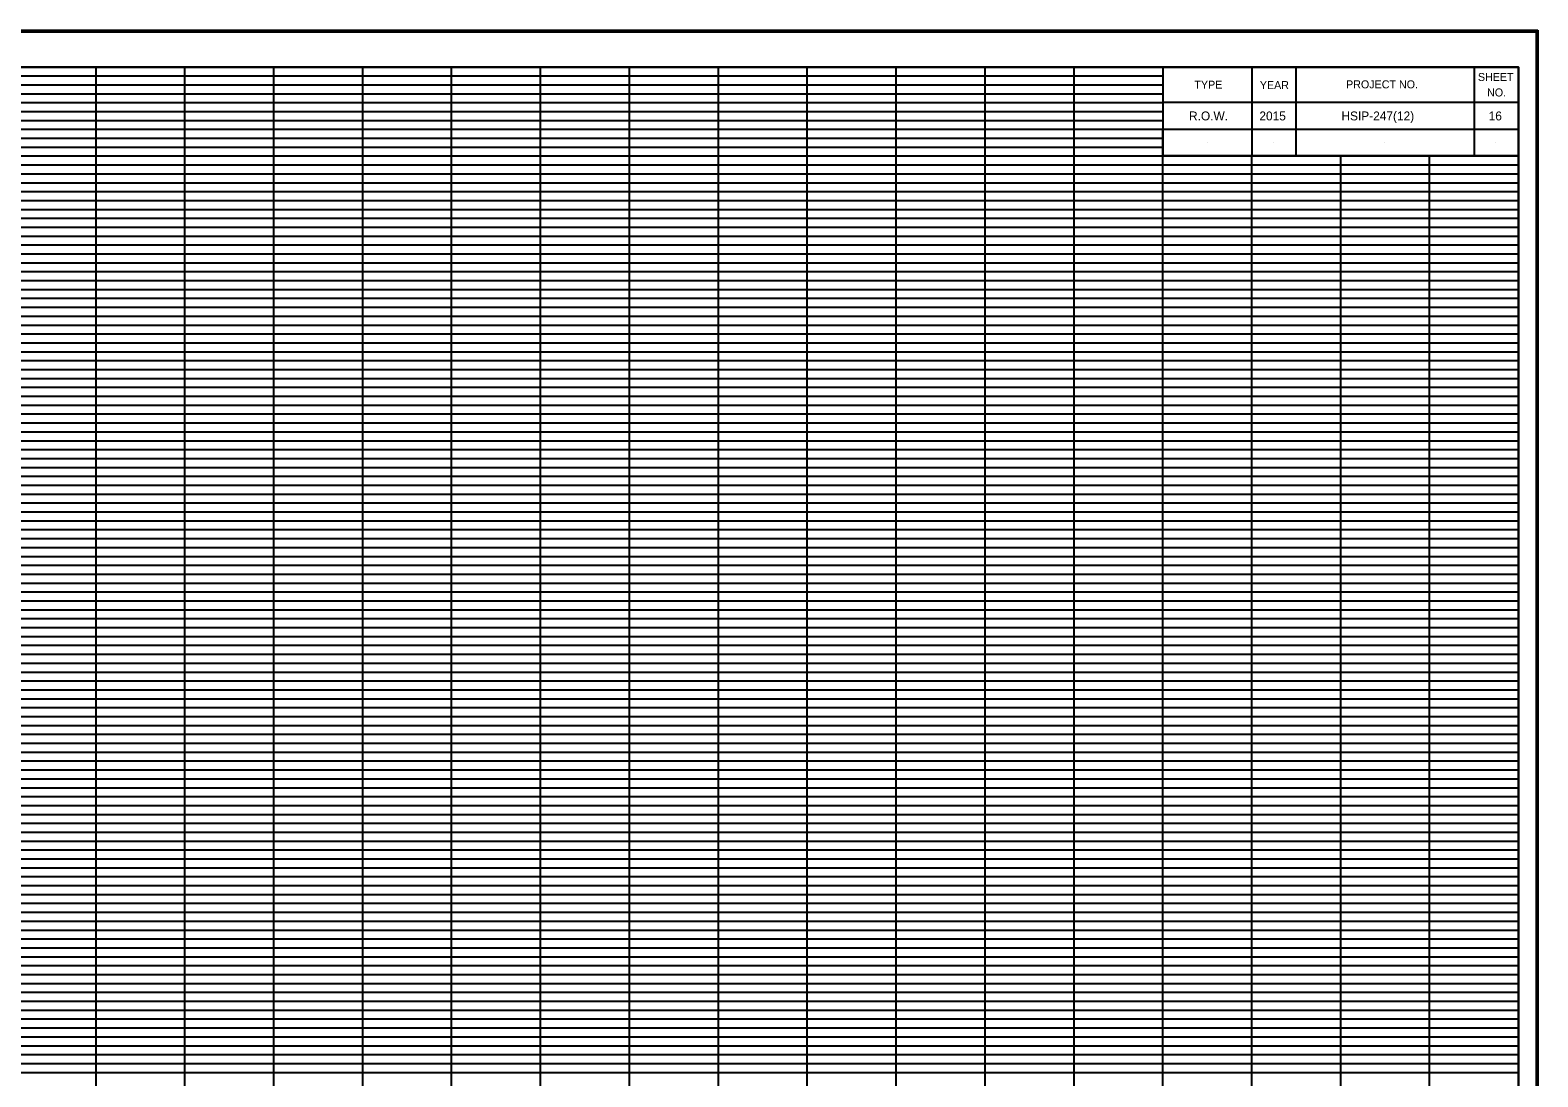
# Model space of a CAD drawing. Extents: x -200 to 1704, y -325 to 2307.
# Drawn here: x 1532.6 to 1702.2, y 1366.5 to 1484.1 of the extents above; entities that cross this region are included whole.
import ezdxf

# ---------------------------------------------------------------- set-up
doc = ezdxf.new("R2010")
doc.units = 0
for name, color, linetype in [('DESIGN - SCRATCH - User 1', 7, 'Continuous'), ('DESIGN - SHEET - Corner Text', 7, 'Continuous'), ('DESIGN - SHEET - Light Grid', 7, 'Continuous'), ('DESIGN - SHEET - Linework', 7, 'Continuous'), ('DESIGN - SHEET - Plot Shape', 7, 'Continuous')]:
    doc.layers.add(name, color=color, linetype=linetype)

msp = doc.modelspace()

# ---------------------------------------------------------------- linework, layer by layer
at = {"layer": 'DESIGN - SCRATCH - User 1'}
for p, q in [((1665, 1474.5), (1665, 1474.5)), ((1672.4, 1474.5), (1672.4, 1474.5)), ((1684.9, 1474.5), (1684.9, 1474.5)), ((1697.4, 1474.5), (1697.4, 1474.5)), ((1665, 1471.5), (1665, 1471.5)), ((1672.4, 1471.5), (1672.4, 1471.5)), ((1684.9, 1471.5), (1684.9, 1471.5)), ((1697.4, 1471.5), (1697.4, 1471.5))]:
    msp.add_line(p, q, dxfattribs=at)
at = {"layer": 'DESIGN - SHEET - Light Grid'}
for p, q in [((1460, 1479), (1540, 1479)), ((1540, 1479), (1620, 1479)), ((1620, 1479), (1660, 1479)), ((1460, 1478), (1540, 1478)), ((1540, 1478), (1620, 1478)), ((1620, 1478), (1660, 1478)), ((1460, 1477), (1540, 1477)), ((1460, 1476), (1540, 1476)), ((1540, 1477), (1620, 1477)), ((1540, 1476), (1620, 1476)), ((1620, 1477), (1660, 1477)), ((1620, 1476), (1660, 1476)), ((1460, 1475), (1540, 1475)), ((1460, 1474), (1540, 1474)), ((1540, 1475), (1620, 1475)), ((1540, 1474), (1620, 1474)), ((1620, 1475), (1660, 1475)), ((1620, 1474), (1660, 1474)), ((1460, 1473), (1540, 1473)), ((1460, 1472), (1540, 1472)), ((1540, 1473), (1620, 1473)), ((1540, 1472), (1620, 1472)), ((1620, 1473), (1660, 1473)), ((1620, 1472), (1660, 1472)), ((1460, 1471), (1540, 1471)), ((1540, 1471), (1620, 1471)), ((1620, 1471), (1660, 1471)), ((1460, 1469), (1540, 1469)), ((1540, 1469), (1620, 1469)), ((1620, 1469), (1700, 1469)), ((1460, 1468), (1540, 1468)), ((1460, 1467), (1540, 1467)), ((1540, 1468), (1620, 1468)), ((1540, 1467), (1620, 1467)), ((1620, 1468), (1700, 1468)), ((1620, 1467), (1700, 1467)), ((1460, 1466), (1540, 1466)), ((1540, 1466), (1620, 1466)), ((1620, 1466), (1700, 1466)), ((1460, 1465), (1540, 1465)), ((1460, 1464), (1540, 1464)), ((1540, 1465), (1620, 1465)), ((1540, 1464), (1620, 1464)), ((1620, 1465), (1700, 1465)), ((1620, 1464), (1700, 1464)), ((1460, 1463), (1540, 1463)), ((1460, 1462), (1540, 1462)), ((1540, 1463), (1620, 1463)), ((1540, 1462), (1620, 1462)), ((1620, 1463), (1700, 1463)), ((1620, 1462), (1700, 1462)), ((1460, 1461), (1540, 1461)), ((1540, 1461), (1620, 1461)), ((1620, 1461), (1700, 1461)), ((1460, 1459), (1540, 1459)), ((1540, 1459), (1620, 1459)), ((1620, 1459), (1700, 1459)), ((1460, 1458), (1540, 1458)), ((1460, 1457), (1540, 1457)), ((1540, 1458), (1620, 1458)), ((1540, 1457), (1620, 1457)), ((1620, 1458), (1700, 1458)), ((1620, 1457), (1700, 1457)), ((1460, 1456), (1540, 1456)), ((1460, 1455), (1540, 1455)), ((1540, 1456), (1620, 1456)), ((1540, 1455), (1620, 1455)), ((1620, 1456), (1700, 1456)), ((1620, 1455), (1700, 1455)), ((1460, 1454), (1540, 1454)), ((1540, 1454), (1620, 1454)), ((1620, 1454), (1700, 1454)), ((1460, 1453), (1540, 1453)), ((1460, 1452), (1540, 1452)), ((1540, 1453), (1620, 1453)), ((1540, 1452), (1620, 1452)), ((1620, 1453), (1700, 1453)), ((1620, 1452), (1700, 1452)), ((1460, 1451), (1540, 1451)), ((1540, 1451), (1620, 1451)), ((1620, 1451), (1700, 1451)), ((1460, 1449), (1540, 1449)), ((1540, 1449), (1620, 1449)), ((1620, 1449), (1700, 1449)), ((1460, 1448), (1540, 1448)), ((1460, 1447), (1540, 1447)), ((1540, 1448), (1620, 1448)), ((1540, 1447), (1620, 1447)), ((1620, 1448), (1700, 1448)), ((1620, 1447), (1700, 1447)), ((1460, 1446), (1540, 1446)), ((1460, 1445), (1540, 1445)), ((1540, 1446), (1620, 1446)), ((1540, 1445), (1620, 1445)), ((1620, 1446), (1700, 1446)), ((1620, 1445), (1700, 1445)), ((1460, 1444), (1540, 1444)), ((1540, 1444), (1620, 1444)), ((1620, 1444), (1700, 1444)), ((1460, 1443), (1540, 1443)), ((1460, 1442), (1540, 1442)), ((1540, 1443), (1620, 1443)), ((1540, 1442), (1620, 1442)), ((1620, 1443), (1700, 1443)), ((1620, 1442), (1700, 1442)), ((1460, 1441), (1540, 1441)), ((1540, 1441), (1620, 1441)), ((1620, 1441), (1700, 1441)), ((1460, 1439), (1540, 1439)), ((1540, 1439), (1620, 1439)), ((1620, 1439), (1700, 1439)), ((1460, 1438), (1540, 1438)), ((1460, 1437), (1540, 1437)), ((1540, 1438), (1620, 1438)), ((1540, 1437), (1620, 1437)), ((1620, 1438), (1700, 1438)), ((1620, 1437), (1700, 1437)), ((1460, 1436), (1540, 1436)), ((1460, 1435), (1540, 1435)), ((1540, 1436), (1620, 1436)), ((1540, 1435), (1620, 1435)), ((1620, 1436), (1700, 1436)), ((1620, 1435), (1700, 1435)), ((1460, 1434), (1540, 1434)), ((1460, 1433), (1540, 1433)), ((1540, 1434), (1620, 1434)), ((1540, 1433), (1620, 1433)), ((1620, 1434), (1700, 1434)), ((1620, 1433), (1700, 1433)), ((1460, 1432), (1540, 1432)), ((1540, 1432), (1620, 1432)), ((1620, 1432), (1700, 1432)), ((1460, 1431), (1540, 1431)), ((1540, 1431), (1620, 1431)), ((1620, 1431), (1700, 1431)), ((1460, 1429), (1540, 1429)), ((1460, 1428), (1540, 1428)), ((1540, 1429), (1620, 1429)), ((1540, 1428), (1620, 1428)), ((1620, 1429), (1700, 1429)), ((1620, 1428), (1700, 1428)), ((1460, 1427), (1540, 1427)), ((1540, 1427), (1620, 1427)), ((1620, 1427), (1700, 1427)), ((1460, 1426), (1540, 1426)), ((1460, 1425), (1540, 1425)), ((1540, 1426), (1620, 1426)), ((1540, 1425), (1620, 1425)), ((1620, 1426), (1700, 1426)), ((1620, 1425), (1700, 1425)), ((1460, 1424), (1540, 1424)), ((1460, 1423), (1540, 1423)), ((1540, 1424), (1620, 1424)), ((1540, 1423), (1620, 1423)), ((1620, 1424), (1700, 1424)), ((1620, 1423), (1700, 1423)), ((1460, 1422), (1540, 1422)), ((1540, 1422), (1620, 1422)), ((1620, 1422), (1700, 1422)), ((1460, 1421), (1540, 1421)), ((1540, 1421), (1620, 1421)), ((1620, 1421), (1700, 1421)), ((1460, 1419), (1540, 1419)), ((1460, 1418), (1540, 1418)), ((1540, 1419), (1620, 1419)), ((1540, 1418), (1620, 1418)), ((1620, 1419), (1700, 1419)), ((1620, 1418), (1700, 1418)), ((1460, 1417), (1540, 1417)), ((1460, 1416), (1540, 1416)), ((1540, 1417), (1620, 1417)), ((1540, 1416), (1620, 1416)), ((1620, 1417), (1700, 1417)), ((1620, 1416), (1700, 1416)), ((1460, 1415), (1540, 1415)), ((1540, 1415), (1620, 1415)), ((1620, 1415), (1700, 1415)), ((1460, 1414), (1540, 1414)), ((1460, 1413), (1540, 1413)), ((1540, 1414), (1620, 1414)), ((1540, 1413), (1620, 1413)), ((1620, 1414), (1700, 1414)), ((1620, 1413), (1700, 1413)), ((1460, 1412), (1540, 1412)), ((1460, 1411), (1540, 1411)), ((1540, 1412), (1620, 1412)), ((1540, 1411), (1620, 1411)), ((1620, 1412), (1700, 1412)), ((1620, 1411), (1700, 1411)), ((1460, 1409), (1540, 1409)), ((1460, 1408), (1540, 1408)), ((1540, 1409), (1620, 1409)), ((1540, 1408), (1620, 1408)), ((1620, 1409), (1700, 1409)), ((1620, 1408), (1700, 1408)), ((1460, 1407), (1540, 1407)), ((1460, 1406), (1540, 1406)), ((1540, 1407), (1620, 1407)), ((1540, 1406), (1620, 1406)), ((1620, 1407), (1700, 1407)), ((1620, 1406), (1700, 1406)), ((1460, 1405), (1540, 1405)), ((1540, 1405), (1620, 1405)), ((1620, 1405), (1700, 1405)), ((1460, 1404), (1540, 1404)), ((1460, 1403), (1540, 1403)), ((1540, 1404), (1620, 1404)), ((1540, 1403), (1620, 1403)), ((1620, 1404), (1700, 1404)), ((1620, 1403), (1700, 1403)), ((1460, 1402), (1540, 1402)), ((1460, 1401), (1540, 1401)), ((1540, 1402), (1620, 1402)), ((1540, 1401), (1620, 1401)), ((1620, 1402), (1700, 1402)), ((1620, 1401), (1700, 1401)), ((1460, 1399), (1540, 1399)), ((1460, 1398), (1540, 1398)), ((1540, 1399), (1620, 1399)), ((1540, 1398), (1620, 1398)), ((1620, 1399), (1700, 1399)), ((1620, 1398), (1700, 1398)), ((1460, 1397), (1540, 1397)), ((1460, 1396), (1540, 1396)), ((1540, 1397), (1620, 1397)), ((1540, 1396), (1620, 1396)), ((1620, 1397), (1700, 1397)), ((1620, 1396), (1700, 1396)), ((1460, 1395), (1540, 1395)), ((1460, 1394), (1540, 1394)), ((1540, 1395), (1620, 1395)), ((1540, 1394), (1620, 1394)), ((1620, 1395), (1700, 1395)), ((1620, 1394), (1700, 1394)), ((1460, 1393), (1540, 1393)), ((1540, 1393), (1620, 1393)), ((1620, 1393), (1700, 1393)), ((1460, 1392), (1540, 1392)), ((1460, 1391), (1540, 1391)), ((1540, 1392), (1620, 1392)), ((1540, 1391), (1620, 1391)), ((1620, 1392), (1700, 1392)), ((1620, 1391), (1700, 1391)), ((1460, 1389), (1540, 1389)), ((1540, 1389), (1620, 1389)), ((1620, 1389), (1700, 1389)), ((1460, 1388), (1540, 1388)), ((1540, 1388), (1620, 1388)), ((1620, 1388), (1700, 1388)), ((1460, 1387), (1540, 1387)), ((1460, 1386), (1540, 1386)), ((1540, 1387), (1620, 1387)), ((1540, 1386), (1620, 1386)), ((1620, 1387), (1700, 1387)), ((1620, 1386), (1700, 1386)), ((1460, 1385), (1540, 1385)), ((1460, 1384), (1540, 1384)), ((1540, 1385), (1620, 1385)), ((1540, 1384), (1620, 1384)), ((1620, 1385), (1700, 1385)), ((1620, 1384), (1700, 1384)), ((1460, 1383), (1540, 1383)), ((1540, 1383), (1620, 1383)), ((1620, 1383), (1700, 1383)), ((1460, 1382), (1540, 1382)), ((1460, 1381), (1540, 1381)), ((1540, 1382), (1620, 1382)), ((1540, 1381), (1620, 1381)), ((1620, 1382), (1700, 1382)), ((1620, 1381), (1700, 1381)), ((1460, 1379), (1540, 1379)), ((1540, 1379), (1620, 1379)), ((1620, 1379), (1700, 1379)), ((1460, 1378), (1540, 1378)), ((1460, 1377), (1540, 1377)), ((1540, 1378), (1620, 1378)), ((1540, 1377), (1620, 1377)), ((1620, 1378), (1700, 1378)), ((1620, 1377), (1700, 1377)), ((1460, 1376), (1540, 1376)), ((1540, 1376), (1620, 1376)), ((1620, 1376), (1700, 1376)), ((1460, 1375), (1540, 1375)), ((1460, 1374), (1540, 1374)), ((1540, 1375), (1620, 1375)), ((1540, 1374), (1620, 1374)), ((1620, 1375), (1700, 1375)), ((1620, 1374), (1700, 1374)), ((1460, 1373), (1540, 1373)), ((1460, 1372), (1540, 1372)), ((1540, 1373), (1620, 1373)), ((1540, 1372), (1620, 1372)), ((1620, 1373), (1700, 1373)), ((1620, 1372), (1700, 1372)), ((1460, 1371), (1540, 1371)), ((1540, 1371), (1620, 1371)), ((1620, 1371), (1700, 1371)), ((1460, 1369), (1540, 1369)), ((1540, 1369), (1620, 1369)), ((1620, 1369), (1700, 1369)), ((1460, 1368), (1540, 1368)), ((1460, 1367), (1540, 1367)), ((1540, 1368), (1620, 1368)), ((1540, 1367), (1620, 1367)), ((1620, 1368), (1700, 1368)), ((1620, 1367), (1700, 1367))]:
    msp.add_line(p, q, dxfattribs=at)
at = {"layer": 'DESIGN - SHEET - Linework'}
for p, q in [((1361.77, 1484.14), (1702.17, 1484.14)), ((1702.17, 1484.14), (1702.17, 1265.86)), ((1540, 1270), (1540, 1480)), ((1550, 1270), (1550, 1480)), ((1560, 1270), (1560, 1480)), ((1570, 1270), (1570, 1480)), ((1580, 1270), (1580, 1480)), ((1590, 1270), (1590, 1480)), ((1600, 1270), (1600, 1480)), ((1610, 1270), (1610, 1480)), ((1620, 1270), (1620, 1480)), ((1630, 1270), (1630, 1480)), ((1640, 1270), (1640, 1480)), ((1650, 1270), (1650, 1480)), ((1380, 1470), (1660, 1470)), ((1660, 1270), (1660, 1470)), ((1670, 1270), (1670, 1470)), ((1680, 1270), (1680, 1470)), ((1690, 1270), (1690, 1470)), ((1380, 1460), (1700, 1460)), ((1380, 1450), (1700, 1450)), ((1380, 1440), (1700, 1440)), ((1380, 1430), (1700, 1430)), ((1380, 1420), (1700, 1420)), ((1380, 1410), (1700, 1410)), ((1380, 1400), (1700, 1400)), ((1380, 1390), (1700, 1390)), ((1380, 1380), (1700, 1380)), ((1380, 1370), (1700, 1370))]:
    msp.add_line(p, q, dxfattribs=at)
for points in [[(1380, 1480), (1380, 1270), (1700, 1270), (1700, 1480), (1380, 1480)], [(1660, 1480), (1660, 1470), (1700, 1470), (1700, 1480), (1695, 1480), (1695, 1470), (1675, 1470), (1675, 1480), (1670, 1480), (1670, 1470), (1700, 1470), (1660, 1470), (1660, 1473), (1700, 1473), (1700, 1476), (1660, 1476)]]:
    msp.add_lwpolyline(points, dxfattribs=at)
at = {"layer": 'DESIGN - SHEET - Plot Shape'}
for points in [[(1361.97, 1483.94), (1701.97, 1483.94), (1701.97, 1266.06), (1361.97, 1266.06)], [(1371.5, 1480), (1700, 1480), (1700, 1267.5), (1371.5, 1267.5)]]:
    msp.add_lwpolyline(points, close=True, dxfattribs=at)

# ---------------------------------------------------------------- texts
at = {"layer": 'DESIGN - SHEET - Corner Text'}
for s, height, p in [('SHEET', 0.9, (1695.43, 1478.43)), ('TYPE', 0.9, (1663.54, 1477.56)), ('YEAR', 0.9, (1670.9, 1477.52)), ('PROJECT NO.', 0.9, (1680.6, 1477.6)), ('NO.', 0.9, (1696.46, 1476.69)), ('R.O.W.', 1, (1662.94, 1474)), ('2015', 1, (1670.85, 1474)), ('HSIP-247(12)', 1, (1680.08, 1474)), ('16', 1, (1696.64, 1474))]:
    msp.add_text(s, height=height, dxfattribs=at).set_placement(p)

doc.saveas('drawing.dxf')
